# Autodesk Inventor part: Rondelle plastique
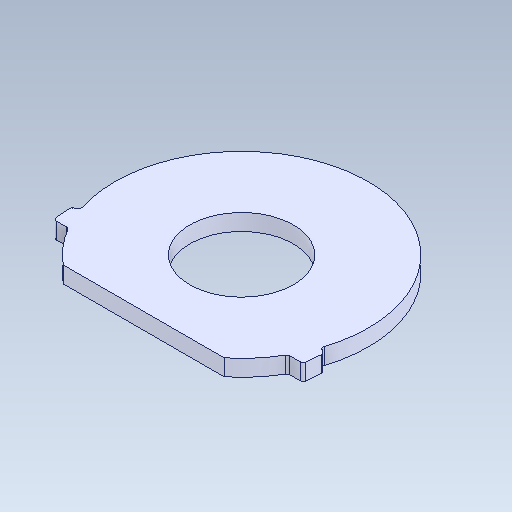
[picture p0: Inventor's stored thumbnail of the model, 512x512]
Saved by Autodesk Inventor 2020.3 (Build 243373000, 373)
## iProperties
Created: 2019-01
Part Number: Rondelle plastique
Material: Générique
Document SubType Name: Modeling
Designer: ficho
Density: 1 g/cm^3
Appearance: Par défaut
Mass: 0.421837 g
Surface Area: 7.32598 cm^2
Volume: 0.421837 cm^3
Sending System: SolidWorks 2015
Last Author: adrien
Last Saved: 2019-01-11
Author: ficho
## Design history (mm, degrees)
node "Boss.-Extru.1"
sketch "Esquisse1"
  geometry: L1 (-10.58, -3.606)-(-10.856, -3.8) reference; L2 (-10.961, -4.028)-(-10.847, -5.273) reference; L3 (-10.598, -5.5)-(-9.67, -5.5) reference; L4 (-6.982, -8.5)-(6.982, -8.5) reference; L5 (9.67, -5.5)-(10.598, -5.5) reference; L6 (10.847, -5.273)-(10.961, -4.028) reference; L7 (10.856, -3.8)-(10.58, -3.606) reference; C1 r 4.5 at (0, 0) reference; A1 r 11 centre (0, 0) between (10.485, -3.326) and (-10.485, -3.326) reference; A2 r 0.25 centre (-10.723, -3.402) between (-10.58, -3.606) and (-10.485, -3.326) reference; A3 r 0.25 centre (-10.712, -4.005) between (-10.856, -3.8) and (-10.961, -4.028) reference; A4 r 0.25 centre (-10.598, -5.25) between (-10.847, -5.273) and (-10.598, -5.5) reference; A5 r 0.25 centre (-9.67, -5.75) between (-9.455, -5.622) and (-9.67, -5.5) reference; A6 r 11 centre (0, 0) between (-9.455, -5.622) and (-6.982, -8.5) reference; A7 r 11 centre (0, 0) between (6.982, -8.5) and (9.455, -5.622) reference; A8 r 0.25 centre (9.67, -5.75) between (9.67, -5.5) and (9.455, -5.622) reference; A9 r 0.25 centre (10.598, -5.25) between (10.598, -5.5) and (10.847, -5.273) reference; A10 r 0.25 centre (10.712, -4.005) between (10.961, -4.028) and (10.856, -3.8) reference; A11 r 0.25 centre (10.723, -3.402) between (10.485, -3.326) and (10.58, -3.606) reference; 1 further point
extrude "Extrusion1" join sketch "Esquisse1" distance "d0" = 0.525; taper "d1" = 0 deg
node "Solide1"
